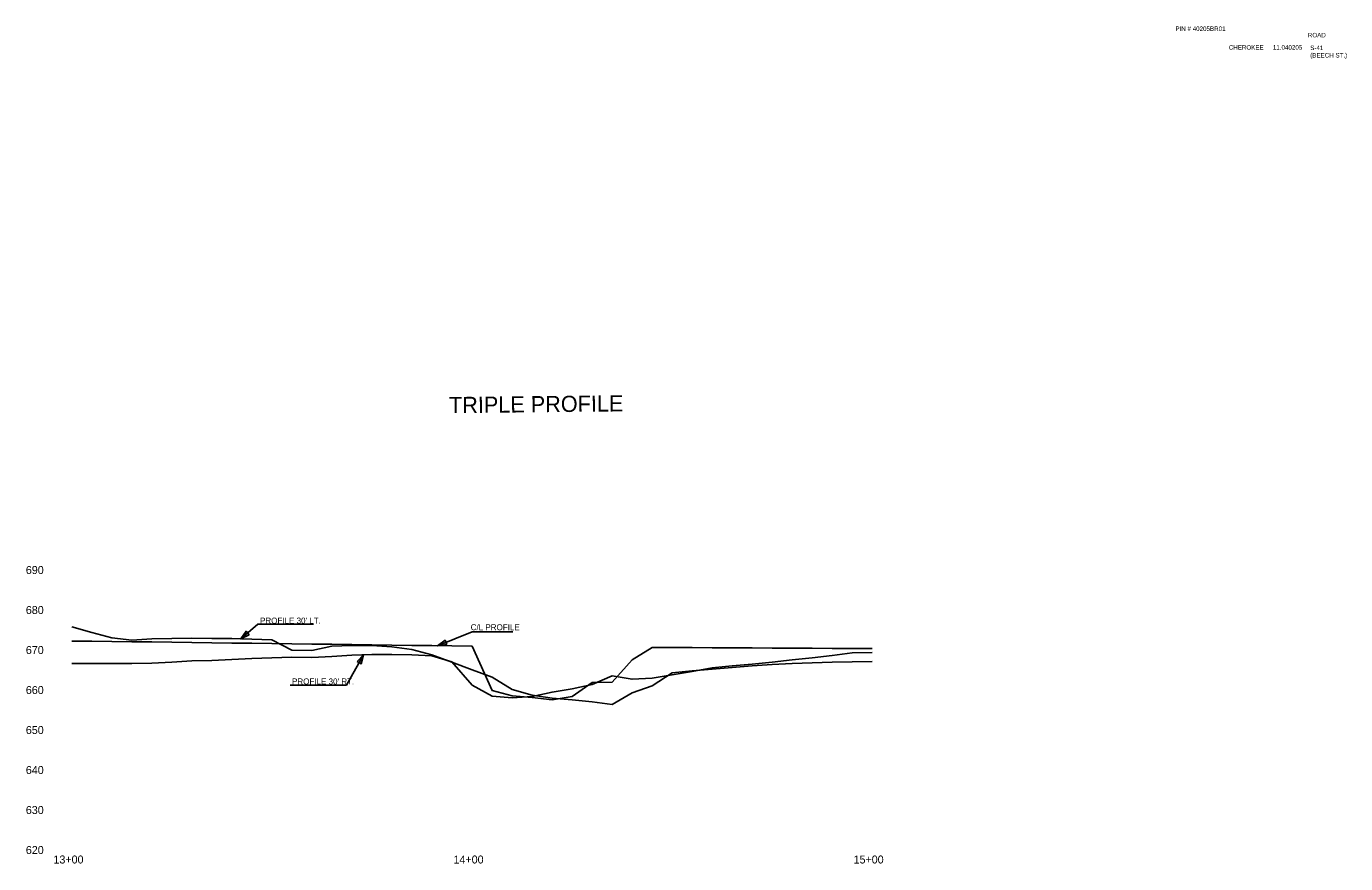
# Model space of a CAD drawing. Extents: x 16382402 to 16388022, y 46194326 to 46202918.
# Drawn here: x 16384860.8 to 16385190.6, y 46202708.4 to 46202917.7 of the extents above; entities that cross this region are included whole.
import ezdxf

# ---------------------------------------------------------------- set-up
doc = ezdxf.new("R2010")
doc.units = 0
for name, color, linetype in [('RD_DDB_ElevTX', 7, 'Continuous'), ('RD_DDB_Profile_EX', 7, 'Continuous'), ('RD_DDB_StaTX', 7, 'Continuous'), ('RD_EX_Misc', 7, 'Continuous'), ('RD_TX_Drainage', 7, 'Continuous'), ('RD_TX_Misc1', 7, 'Continuous')]:
    doc.layers.add(name, color=color, linetype=linetype)

msp = doc.modelspace()

# ---------------------------------------------------------------- linework, layer by layer
at = {"layer": 'RD_DDB_Profile_EX'}
for p, q in [((16384914.41, 46202764.59), (16384918.71, 46202768.29)), ((16384918.71, 46202768.29), (16384932.56, 46202768.29)), ((16384972.22, 46202766.34), (16384963.59, 46202762.88)), ((16384972.22, 46202766.34), (16384982.44, 46202766.34)), ((16384940.87, 46202752.98), (16384945.13, 46202760.62)), ((16384926.75, 46202752.98), (16384940.87, 46202752.98))]:
    msp.add_line(p, q, dxfattribs=at)
for points in [[(16384872.21, 46202767.59), (16384877.21, 46202766.2), (16384882.21, 46202764.86), (16384887.21, 46202764.24), (16384892.21, 46202764.59), (16384897.21, 46202764.68), (16384902.21, 46202764.73), (16384907.21, 46202764.72), (16384912.21, 46202764.64), (16384917.21, 46202764.54), (16384922.21, 46202764.33), (16384927.21, 46202761.76), (16384932.21, 46202761.69), (16384937.21, 46202762.8), (16384942.21, 46202762.91), (16384947.21, 46202762.95), (16384952.21, 46202762.6), (16384957.21, 46202761.97), (16384962.21, 46202760.62), (16384967.21, 46202758.74), (16384972.21, 46202756.86), (16384977.21, 46202754.98), (16384982.21, 46202751.94), (16384987.21, 46202750.5), (16384992.21, 46202749.8), (16384997.21, 46202749.32), (16385002.21, 46202748.85), (16385007.21, 46202748.18), (16385012.21, 46202751.11), (16385017.21, 46202752.88), (16385022.21, 46202756.06), (16385027.21, 46202756.58), (16385032.21, 46202757.05), (16385037.21, 46202757.46), (16385042.21, 46202757.82), (16385047.21, 46202758.14), (16385052.21, 46202758.41), (16385057.21, 46202758.62), (16385062.21, 46202758.78), (16385067.21, 46202758.86), (16385072.21, 46202758.89)], [(16384872.21, 46202764.03), (16384877.21, 46202763.99), (16384882.21, 46202763.93), (16384887.21, 46202763.87), (16384892.21, 46202763.81), (16384897.21, 46202763.76), (16384902.21, 46202763.69), (16384907.21, 46202763.62), (16384912.21, 46202763.55), (16384917.21, 46202763.48), (16384922.21, 46202763.41), (16384927.21, 46202763.35), (16384932.21, 46202763.29), (16384937.21, 46202763.23), (16384942.21, 46202763.17), (16384947.21, 46202763.09), (16384952.21, 46202763.01), (16384957.21, 46202762.95), (16384962.21, 46202762.9), (16384967.21, 46202762.84), (16384972.21, 46202762.78), (16384977.21, 46202751.7), (16384982.21, 46202750.34), (16384987.21, 46202749.9), (16384992.21, 46202749.36), (16384997.21, 46202750.2), (16385002.21, 46202753.64), (16385007.21, 46202753.73), (16385012.21, 46202759.31), (16385017.21, 46202762.46), (16385022.21, 46202762.43), (16385027.21, 46202762.39), (16385032.21, 46202762.36), (16385037.21, 46202762.33), (16385042.21, 46202762.33), (16385047.21, 46202762.3), (16385052.21, 46202762.27), (16385057.21, 46202762.24), (16385062.21, 46202762.2), (16385067.21, 46202762.17), (16385072.21, 46202762.17)], [(16384872.21, 46202758.47), (16384877.21, 46202758.42), (16384882.21, 46202758.42), (16384887.21, 46202758.46), (16384892.21, 46202758.5), (16384897.21, 46202758.74), (16384902.21, 46202759.06), (16384907.21, 46202759.16), (16384912.21, 46202759.4), (16384917.21, 46202759.64), (16384922.21, 46202759.87), (16384927.21, 46202759.98), (16384932.21, 46202759.96), (16384937.21, 46202760.22), (16384942.21, 46202760.55), (16384947.21, 46202760.66), (16384952.21, 46202760.64), (16384957.21, 46202760.62), (16384962.21, 46202760.33), (16384967.21, 46202758.88), (16384972.21, 46202753.02), (16384977.21, 46202750.23), (16384982.21, 46202749.86), (16384987.21, 46202750.14), (16384992.21, 46202751.3), (16384997.21, 46202752.06), (16385002.21, 46202753.14), (16385007.21, 46202755.37), (16385012.21, 46202754.48), (16385017.21, 46202754.8), (16385022.21, 46202755.57), (16385027.21, 46202756.41), (16385032.21, 46202757.34), (16385037.21, 46202757.86), (16385042.21, 46202758.29), (16385047.21, 46202758.76), (16385052.21, 46202759.31), (16385057.21, 46202759.87), (16385062.21, 46202760.45), (16385067.21, 46202761.09), (16385072.21, 46202761.19)]]:
    msp.add_lwpolyline(points, dxfattribs=at)
at = {"layer": 'RD_TX_Drainage'}
for points in [[(16384916.48, 46202765.63), (16384914.41, 46202764.59), (16384915.75, 46202766.49)], [(16384965.89, 46202763.2), (16384963.59, 46202762.88), (16384965.47, 46202764.24)], [(16384943.54, 46202758.92), (16384945.13, 46202760.62), (16384944.53, 46202758.38)]]:
    msp.add_lwpolyline(points, close=True, dxfattribs=at)

# ---------------------------------------------------------------- texts
at = {"layer": 'RD_DDB_ElevTX'}
for s, p in [('690', (16384860.69, 46202780.8)), ('680', (16384860.69, 46202770.8)), ('670', (16384860.69, 46202760.8)), ('660', (16384860.69, 46202750.8)), ('650', (16384860.69, 46202740.8)), ('640', (16384860.69, 46202730.8)), ('630', (16384860.69, 46202720.8)), ('620', (16384860.69, 46202710.8))]:
    msp.add_text(s, height=2, dxfattribs=at).set_placement(p)
at = {"layer": 'RD_DDB_Profile_EX'}
for s, p in [("PROFILE 30' LT.", (16384919.23, 46202768.41)), ('C/L PROFILE ', (16384971.88, 46202766.75)), ("PROFILE 30' RT.", (16384927.23, 46202753.19))]:
    msp.add_text(s, height=1.5, dxfattribs=at).set_placement(p)
at = {"layer": 'RD_DDB_StaTX'}
for s, p in [('13+00', (16384867.59, 46202708.43)), ('14+00', (16384967.59, 46202708.43)), ('15+00', (16385067.59, 46202708.43))]:
    msp.add_text(s, height=2, dxfattribs=at).set_placement(p)
at = {"layer": 'RD_EX_Misc'}
for s, p in [('PIN # 40205BR01', (16385148.04, 46202916.57)), ('ROAD', (16385181.14, 46202914.97)), ('CHEROKEE', (16385161.38, 46202911.9)), ('11.040205', (16385172.4, 46202911.9)), ('S-41', (16385181.73, 46202911.79)), ('(BEECH ST.)', (16385181.73, 46202909.93))]:
    msp.add_text(s, height=1.125, dxfattribs=at).set_placement(p)
at = {"layer": 'RD_TX_Misc1'}
msp.add_text('TRIPLE PROFILE', height=4.0437, rotation=0.594, dxfattribs=at).set_placement((16384966.49, 46202821.01))

doc.saveas('drawing.dxf')
